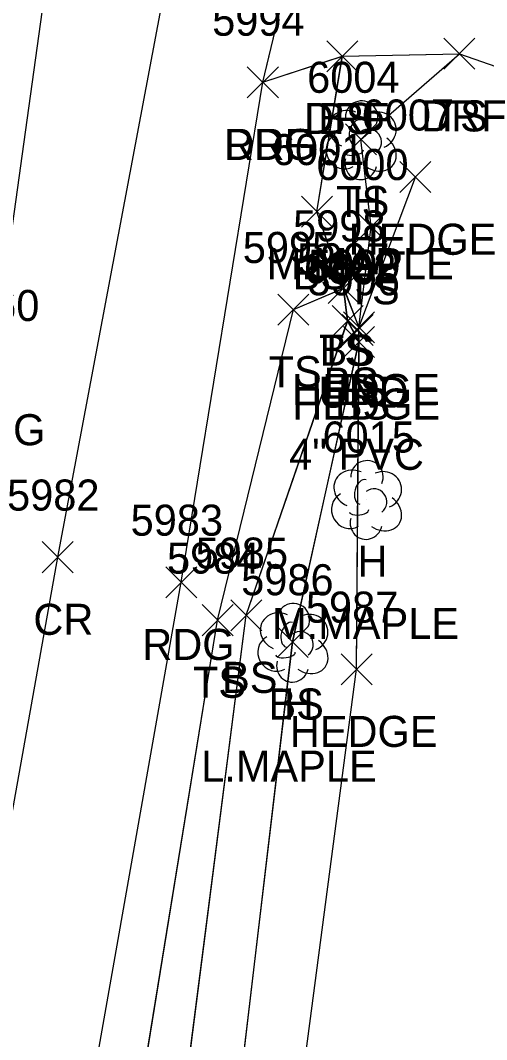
# Model space of a CAD drawing. Extents: x 1554668 to 1563881, y 831386 to 834374.
# Drawn here: x 1561932.8 to 1561962.8, y 834064.9 to 834130.6 of the extents above; entities that cross this region are included whole.
import ezdxf

# ---------------------------------------------------------------- set-up
doc = ezdxf.new("R2010")
doc.units = 0
for name, color, linetype in [('D_A', 7, 'Continuous'), ('D_C', 7, 'Continuous'), ('D_I', 7, 'Continuous'), ('D_TIC', 7, 'Continuous'), ('L_A', 7, 'Continuous'), ('L_C', 7, 'Continuous'), ('L_I', 7, 'Continuous'), ('L_TIC', 7, 'Continuous'), ('LAHR', 7, 'Continuous'), ('LELB', 7, 'Continuous'), ('LTD', 7, 'Continuous'), ('P_A', 7, 'Continuous'), ('P_I', 7, 'Continuous'), ('P_TIC', 7, 'Continuous'), ('PEU', 7, 'Continuous'), ('PRC', 7, 'Continuous'), ('R_A', 7, 'Continuous'), ('R_I', 7, 'Continuous'), ('R_TIC', 7, 'Continuous'), ('RDF', 7, 'Continuous')]:
    doc.layers.add(name, color=color, linetype=linetype)

msp = doc.modelspace()

# ---------------------------------------------------------------- linework, layer by layer
at = {"layer": 'D_TIC'}
for points in [[(1561953.528, 834109.622), (1561955.528, 834111.622)], [(1561955.528, 834109.622), (1561953.528, 834111.622)]]:
    msp.add_lwpolyline(points, dxfattribs=at)
at = {"layer": 'L_TIC'}
for points in [[(1561960.073, 834127.412), (1561962.073, 834129.412)], [(1561962.073, 834127.412), (1561960.073, 834129.412)], [(1561952.536, 834127.252), (1561954.536, 834129.252)], [(1561954.536, 834127.252), (1561952.536, 834129.252)], [(1561953.733, 834121.898), (1561955.733, 834123.898)], [(1561955.733, 834121.898), (1561953.733, 834123.898)], [(1561957.242, 834119.47), (1561959.242, 834121.47)], [(1561959.242, 834119.47), (1561957.242, 834121.47)], [(1561950.9, 834117.244), (1561952.9, 834119.244)], [(1561952.9, 834117.244), (1561950.9, 834119.244)], [(1561954.4, 834116.28), (1561956.4, 834118.28)], [(1561956.4, 834116.28), (1561954.4, 834118.28)], [(1561952.624, 834112.329), (1561954.624, 834114.329)], [(1561954.624, 834112.329), (1561952.624, 834114.329)], [(1561952.624, 834112.329), (1561954.624, 834114.329)], [(1561954.624, 834112.329), (1561952.624, 834114.329)], [(1561949.385, 834110.94), (1561951.385, 834112.94)], [(1561951.385, 834110.94), (1561949.385, 834112.94)], [(1561952.88, 834110.21), (1561954.88, 834112.21)], [(1561954.88, 834110.21), (1561952.88, 834112.21)], [(1561952.88, 834110.21), (1561954.88, 834112.21)], [(1561954.88, 834110.21), (1561952.88, 834112.21)], [(1561953.6, 834109.792), (1561955.6, 834111.792)], [(1561955.6, 834109.792), (1561953.6, 834111.792)], [(1561953.6, 834109.792), (1561955.6, 834111.792)], [(1561955.6, 834109.792), (1561953.6, 834111.792)], [(1561953.612, 834108.857), (1561955.612, 834110.857)], [(1561955.612, 834108.857), (1561953.612, 834110.857)], [(1561953.612, 834108.857), (1561955.612, 834110.857)], [(1561955.612, 834108.857), (1561953.612, 834110.857)], [(1561946.352, 834091.259), (1561948.352, 834093.259)], [(1561948.352, 834091.259), (1561946.352, 834093.259)], [(1561944.507, 834090.941), (1561946.507, 834092.941)], [(1561946.507, 834090.941), (1561944.507, 834092.941)], [(1561949.337, 834089.544), (1561951.337, 834091.544)], [(1561951.337, 834089.544), (1561949.337, 834091.544)], [(1561953.45, 834087.78), (1561955.45, 834089.78)], [(1561955.45, 834087.78), (1561953.45, 834089.78)]]:
    msp.add_lwpolyline(points, dxfattribs=at)
at = {"layer": 'LAHR'}
for points in [[(1561933.167, 833967.71), (1561943.911, 834017.246), (1561949.017, 834047.561), (1561954.45, 834088.78), (1561954.612, 834109.857), (1561954.6, 834110.792), (1561958.242, 834120.47)], [(1561933.168, 833967.708), (1561943.915, 834017.245), (1561949.015, 834047.561), (1561954.446, 834088.779), (1561954.608, 834109.856), (1561954.596, 834110.792), (1561958.243, 834120.47)], [(1561933.168, 833967.708), (1561943.915, 834017.245), (1561949.015, 834047.561), (1561954.446, 834088.779), (1561954.608, 834109.856), (1561954.596, 834110.792), (1561958.243, 834120.47)], [(1561933.168, 833967.708), (1561943.915, 834017.245), (1561949.015, 834047.561), (1561954.446, 834088.779), (1561954.608, 834109.856), (1561954.596, 834110.792), (1561958.243, 834120.47)]]:
    msp.add_lwpolyline(points, dxfattribs=at)
at = {"layer": 'LELB'}
for points in [[(1561890.593, 833773.388), (1561895.718, 833803.087), (1561903.038, 833845.228), (1561912.563, 833892.473), (1561912.525, 833900.106), (1561918.864, 833934.137), (1561920.901, 833947.117), (1561925.493, 833972.113), (1561933.777, 834019.881), (1561938.561, 834049.203), (1561945.505, 834091.941), (1561950.385, 834111.94), (1561953.62, 834113.327), (1561954.596, 834110.792), (1561955.401, 834117.28), (1561954.736, 834122.9), (1561961.072, 834128.412)], [(1561890.593, 833773.388), (1561895.718, 833803.087), (1561903.038, 833845.228), (1561912.563, 833892.473), (1561912.525, 833900.106), (1561918.864, 833934.137), (1561920.901, 833947.117), (1561925.493, 833972.113), (1561933.777, 834019.881), (1561938.561, 834049.203), (1561945.505, 834091.941), (1561950.385, 834111.94), (1561953.62, 834113.327), (1561954.596, 834110.792), (1561955.401, 834117.28), (1561954.736, 834122.9), (1561961.072, 834128.412)], [(1561890.593, 833773.388), (1561895.718, 833803.087), (1561903.038, 833845.228), (1561912.563, 833892.473), (1561912.525, 833900.106), (1561918.864, 833934.137), (1561920.901, 833947.117), (1561925.493, 833972.113), (1561933.777, 834019.881), (1561938.561, 834049.203), (1561945.505, 834091.941), (1561950.385, 834111.94), (1561953.62, 834113.327), (1561954.596, 834110.792), (1561955.401, 834117.28), (1561954.736, 834122.9), (1561961.072, 834128.412)], [(1561890.594, 833773.393), (1561895.717, 833803.083), (1561903.038, 833845.232), (1561912.562, 833892.472), (1561912.525, 833900.111), (1561918.862, 833934.133), (1561920.9, 833947.114), (1561925.493, 833972.114), (1561933.775, 834019.878), (1561938.557, 834049.204), (1561945.507, 834091.941), (1561950.385, 834111.94), (1561953.624, 834113.329), (1561954.6, 834110.792), (1561955.4, 834117.28), (1561954.733, 834122.898), (1561961.073, 834128.412)], [(1561923.916, 833946.356), (1561928.443, 833971.918), (1561936.647, 834019.209), (1561937.553, 834020.454), (1561941.755, 834048.637), (1561947.352, 834092.259), (1561953.88, 834111.21), (1561953.624, 834113.329), (1561951.9, 834118.244), (1561953.536, 834128.252)], [(1561923.917, 833946.355), (1561928.444, 833971.915), (1561936.648, 834019.206), (1561937.556, 834020.453), (1561941.757, 834048.637), (1561947.351, 834092.259), (1561953.877, 834111.209), (1561953.62, 834113.327), (1561951.896, 834118.243), (1561953.535, 834128.252)], [(1561923.917, 833946.355), (1561928.444, 833971.915), (1561936.648, 834019.206), (1561937.556, 834020.453), (1561941.757, 834048.637), (1561947.351, 834092.259), (1561953.877, 834111.209), (1561953.62, 834113.327), (1561951.896, 834118.243), (1561953.535, 834128.252)], [(1561923.917, 833946.355), (1561928.444, 833971.915), (1561936.648, 834019.206), (1561937.556, 834020.453), (1561941.757, 834048.637), (1561947.351, 834092.259), (1561953.877, 834111.209), (1561953.62, 834113.327), (1561951.896, 834118.243), (1561953.535, 834128.252)], [(1561956.838, 833935.82), (1561944.784, 833952.217), (1561933.167, 833967.71), (1561942.405, 834017.989), (1561945.385, 834048.678), (1561950.337, 834090.544), (1561954.612, 834109.857), (1561953.88, 834111.21)], [(1561956.839, 833935.82), (1561944.785, 833952.215), (1561933.168, 833967.708), (1561942.401, 834017.991), (1561945.381, 834048.679), (1561950.339, 834090.544), (1561954.608, 834109.856), (1561953.877, 834111.209)], [(1561956.839, 833935.82), (1561944.785, 833952.215), (1561933.168, 833967.708), (1561942.401, 834017.991), (1561945.381, 834048.679), (1561950.339, 834090.544), (1561954.608, 834109.856), (1561953.877, 834111.209)], [(1561956.839, 833935.82), (1561944.785, 833952.215), (1561933.168, 833967.708), (1561942.401, 834017.991), (1561945.381, 834048.679), (1561950.339, 834090.544), (1561954.608, 834109.856), (1561953.877, 834111.209)]]:
    msp.add_lwpolyline(points, dxfattribs=at)
at = {"layer": 'LTD'}
for p, q in [((1561954.733, 834122.898), (1561954.733, 834122.898)), ((1561954.733, 834122.898), (1561954.733, 834122.898)), ((1561955.075, 834099.735), (1561955.075, 834099.735)), ((1561955.075, 834099.735), (1561955.075, 834099.735)), ((1561950.337, 834090.544), (1561950.337, 834090.544)), ((1561950.337, 834090.544), (1561950.337, 834090.544))]:
    msp.add_line(p, q, dxfattribs=at)
for centre in [(1561954.779, 834124.332), (1561955.121, 834101.169), (1561950.383, 834091.978)]:
    msp.add_arc(centre, 1.047, 335.52715, 180.95627, dxfattribs=at)
for centre, major_axis, ratio, start_param, end_param in [((1561953.941, 834123.565), (1.21, -0.512), 0.895232, 1.570796, 4.712389), ((1561955.774, 834123.482), (-1.141, -0.483), 0.949671, 1.570796, 4.712389), ((1561954.524, 834123.357), (-0.208, -0.792), 0.645439, 3.141593, 6.283185), ((1561955.233, 834122.732), (-0.5, 0.667), 0.989748, 3.141593, 6.283185), ((1561953.649, 834122.19), (0.584, -1.042), 0.959034, 3.141593, 6.283185), ((1561955.733, 834122.065), (-1.09, 0.792), 0.841452, 1.570796, 4.712389), ((1561954.274, 834122.148), (-0.625, -0.083), 0.423636, 0, 3.141593), ((1561954.733, 834121.398), (0.265, 1.061), 0.942809, 1.570796, 4.712389), ((1561954.283, 834100.401), (1.21, -0.512), 0.895232, 1.570796, 4.712389), ((1561956.116, 834100.318), (-1.141, -0.483), 0.949671, 1.570796, 4.712389), ((1561954.866, 834100.193), (-0.208, -0.792), 0.645439, 3.141593, 6.283185), ((1561955.575, 834099.568), (-0.5, 0.667), 0.989748, 3.141593, 6.283185), ((1561953.992, 834099.026), (0.584, -1.042), 0.959034, 3.141593, 6.283185), ((1561956.075, 834098.901), (-1.09, 0.792), 0.841452, 1.570796, 4.712389), ((1561955.075, 834098.235), (0.265, 1.061), 0.942809, 1.570796, 4.712389), ((1561954.617, 834098.985), (-0.625, -0.083), 0.423636, 0, 3.141593), ((1561949.545, 834091.211), (1.21, -0.512), 0.895232, 1.570796, 4.712389), ((1561951.378, 834091.128), (-1.141, -0.483), 0.949671, 1.570796, 4.712389), ((1561950.128, 834091.003), (-0.208, -0.792), 0.645439, 3.141593, 6.283185), ((1561950.837, 834090.378), (-0.5, 0.667), 0.989748, 3.141593, 6.283185), ((1561949.253, 834089.836), (0.584, -1.042), 0.959034, 3.141593, 6.283185), ((1561951.337, 834089.711), (-1.09, 0.792), 0.841452, 1.570796, 4.712389), ((1561950.337, 834089.044), (0.265, 1.061), 0.942809, 1.570796, 4.712389), ((1561949.878, 834089.794), (-0.625, -0.083), 0.423636, 0, 3.141593)]:
    msp.add_ellipse(centre, major_axis=major_axis, ratio=ratio, start_param=start_param, end_param=end_param, dxfattribs=at)
at = {"layer": 'P_TIC'}
for points in [[(1561947.417, 834125.574), (1561949.417, 834127.574)], [(1561949.417, 834125.574), (1561947.417, 834127.574)], [(1561934.214, 834094.998), (1561936.214, 834096.998)], [(1561936.214, 834094.998), (1561934.214, 834096.998)], [(1561942.167, 834093.381), (1561944.167, 834095.381)], [(1561944.167, 834093.381), (1561942.167, 834095.381)]]:
    msp.add_lwpolyline(points, dxfattribs=at)
at = {"layer": 'PEU'}
for points in [[(1561919.943, 834298.234), (1561943.28, 834270.95), (1561951.487, 834242.498), (1561947.428, 834199.982), (1561938.335, 834160.955), (1561930.989, 834108.205), (1561926.196, 834084.148), (1561918.625, 834048.817), (1561911.303, 834007.014), (1561902.907, 833960.116), (1561894.327, 833910.706), (1561885.392, 833863.263), (1561878.367, 833822.842), (1561871.83, 833787.475), (1561866.706, 833759.336), (1561861.912, 833735.821)], [(1561919.942, 834298.234), (1561943.28, 834270.951), (1561951.486, 834242.497), (1561947.431, 834199.985), (1561938.334, 834160.954), (1561930.992, 834108.207), (1561926.199, 834084.149), (1561918.629, 834048.816), (1561911.301, 834007.016), (1561902.906, 833960.119), (1561894.326, 833910.708), (1561885.391, 833863.267), (1561878.367, 833822.843), (1561871.83, 833787.477), (1561866.708, 833759.341), (1561861.913, 833735.821)], [(1561919.942, 834298.234), (1561943.28, 834270.951), (1561951.486, 834242.497), (1561947.431, 834199.985), (1561938.334, 834160.954), (1561930.992, 834108.207), (1561926.199, 834084.149), (1561918.629, 834048.816), (1561911.301, 834007.016), (1561902.906, 833960.119), (1561894.326, 833910.708), (1561885.391, 833863.267), (1561878.367, 833822.843), (1561871.83, 833787.477), (1561866.708, 833759.341), (1561861.913, 833735.821)], [(1561919.942, 834298.234), (1561943.28, 834270.951), (1561951.486, 834242.497), (1561947.431, 834199.985), (1561938.334, 834160.954), (1561930.992, 834108.207), (1561926.199, 834084.149), (1561918.629, 834048.816), (1561911.301, 834007.016), (1561902.906, 833960.119), (1561894.326, 833910.708), (1561885.391, 833863.267), (1561878.367, 833822.843), (1561871.83, 833787.477), (1561866.708, 833759.341), (1561861.913, 833735.821)], [(1561874.546, 833715.874), (1561887.478, 833772.584), (1561893.313, 833803.99), (1561901.362, 833845.453), (1561909.68, 833892.69), (1561910.734, 833900.622), (1561917.511, 833934.31), (1561919.487, 833947.442), (1561923.612, 833973.077), (1561931.593, 834020.004), (1561935.393, 834050.314), (1561943.165, 834094.381), (1561948.419, 834126.576), (1561953.285, 834146.878), (1561956.677, 834158.88)], [(1561874.546, 833715.874), (1561887.478, 833772.584), (1561893.313, 833803.99), (1561901.362, 833845.453), (1561909.68, 833892.69), (1561910.734, 833900.622), (1561917.511, 833934.31), (1561919.487, 833947.442), (1561923.612, 833973.077), (1561931.593, 834020.004), (1561935.393, 834050.314), (1561943.165, 834094.381), (1561948.419, 834126.576), (1561953.285, 834146.878), (1561956.677, 834158.88)], [(1561874.546, 833715.874), (1561887.478, 833772.584), (1561893.313, 833803.99), (1561901.362, 833845.453), (1561909.68, 833892.69), (1561910.734, 833900.622), (1561917.511, 833934.31), (1561919.487, 833947.442), (1561923.612, 833973.077), (1561931.593, 834020.004), (1561935.393, 834050.314), (1561943.165, 834094.381), (1561948.419, 834126.576), (1561953.285, 834146.878), (1561956.677, 834158.88)], [(1561874.547, 833715.877), (1561887.477, 833772.582), (1561893.312, 833803.991), (1561901.361, 833845.451), (1561909.679, 833892.687), (1561910.732, 833900.62), (1561917.51, 833934.306), (1561919.486, 833947.443), (1561923.61, 833973.073), (1561931.592, 834020.003), (1561935.394, 834050.314), (1561943.167, 834094.381), (1561948.417, 834126.574), (1561953.283, 834146.877), (1561956.677, 834158.88)]]:
    msp.add_lwpolyline(points, dxfattribs=at)
at = {"layer": 'PRC'}
for points in [[(1561800.21, 833371.538), (1561806.437, 833405.192), (1561812.654, 833434.931), (1561820.127, 833472.189), (1561827.528, 833505.749), (1561836.938, 833558.608), (1561848.037, 833617.29), (1561858.182, 833669.762), (1561866.962, 833717.246), (1561878.604, 833773.781), (1561885.024, 833806.831), (1561891.658, 833847.81), (1561899.783, 833893.72), (1561902.023, 833902.922), (1561908.115, 833944.075), (1561914.56, 833974.526), (1561922.248, 834021.375), (1561927.368, 834052.029), (1561935.214, 834095.998), (1561945.529, 834150.774)], [(1561800.212, 833371.537), (1561806.439, 833405.19), (1561812.656, 833434.927), (1561820.128, 833472.18), (1561827.529, 833505.744), (1561836.939, 833558.603), (1561848.037, 833617.288), (1561858.18, 833669.759), (1561866.961, 833717.243), (1561878.605, 833773.781), (1561885.024, 833806.829), (1561891.662, 833847.808), (1561899.784, 833893.716), (1561902.024, 833902.921), (1561908.116, 833944.071), (1561914.561, 833974.522), (1561922.249, 834021.372), (1561927.371, 834052.029), (1561935.212, 834095.998), (1561945.527, 834150.773)], [(1561800.212, 833371.537), (1561806.439, 833405.19), (1561812.656, 833434.927), (1561820.128, 833472.18), (1561827.529, 833505.744), (1561836.939, 833558.603), (1561848.037, 833617.288), (1561858.18, 833669.759), (1561866.961, 833717.243), (1561878.605, 833773.781), (1561885.024, 833806.829), (1561891.662, 833847.808), (1561899.784, 833893.716), (1561902.024, 833902.921), (1561908.116, 833944.071), (1561914.561, 833974.522), (1561922.249, 834021.372), (1561927.371, 834052.029), (1561935.212, 834095.998), (1561945.527, 834150.773)], [(1561800.212, 833371.537), (1561806.439, 833405.19), (1561812.656, 833434.927), (1561820.128, 833472.18), (1561827.529, 833505.744), (1561836.939, 833558.603), (1561848.037, 833617.288), (1561858.18, 833669.759), (1561866.961, 833717.243), (1561878.605, 833773.781), (1561885.024, 833806.829), (1561891.662, 833847.808), (1561899.784, 833893.716), (1561902.024, 833902.921), (1561908.116, 833944.071), (1561914.561, 833974.522), (1561922.249, 834021.372), (1561927.371, 834052.029), (1561935.212, 834095.998), (1561945.527, 834150.773)]]:
    msp.add_lwpolyline(points, dxfattribs=at)
at = {"layer": 'R_TIC'}
for points in [[(1561960.073, 834127.412), (1561962.073, 834129.412)], [(1561962.073, 834127.412), (1561960.073, 834129.412)], [(1561952.536, 834127.252), (1561954.536, 834129.252)], [(1561954.536, 834127.252), (1561952.536, 834129.252)], [(1561947.417, 834125.574), (1561949.417, 834127.574)], [(1561949.417, 834125.574), (1561947.417, 834127.574)]]:
    msp.add_lwpolyline(points, dxfattribs=at)
at = {"layer": 'RDF'}
for points in [[(1561948.417, 834126.574), (1561953.536, 834128.252), (1561961.073, 834128.412), (1561971.48, 834124.79), (1561973.395, 834137.986), (1561961.731, 834141.224), (1561953.283, 834146.877)], [(1561948.419, 834126.576), (1561953.535, 834128.252), (1561961.072, 834128.412), (1561971.478, 834124.789), (1561973.394, 834137.986), (1561961.727, 834141.222), (1561953.285, 834146.878)], [(1561948.419, 834126.576), (1561953.535, 834128.252), (1561961.072, 834128.412), (1561971.478, 834124.789), (1561973.394, 834137.986), (1561961.727, 834141.222), (1561953.285, 834146.878)], [(1561948.419, 834126.576), (1561953.535, 834128.252), (1561961.072, 834128.412), (1561971.478, 834124.789), (1561973.394, 834137.986), (1561961.727, 834141.222), (1561953.285, 834146.878)]]:
    msp.add_lwpolyline(points, dxfattribs=at)

# ---------------------------------------------------------------- texts
at = {"layer": 'D_A'}
msp.add_text('UND', height=2, dxfattribs=at).set_placement((1561952.001, 834105.622))
at = {"layer": 'D_C'}
msp.add_text('4" PVC', height=2, dxfattribs=at).set_placement((1561950.111, 834101.622))
at = {"layer": 'D_I'}
msp.add_text('6002', height=2, dxfattribs=at).set_placement((1561951.064, 834113.622))
at = {"layer": 'L_A'}
for s, p in [('TS', (1561959.482, 834123.412)), ('BS', (1561951.977, 834123.252)), ('TS', (1561953.142, 834117.898)), ('H', (1561954.166, 834117.898)), ('HEDGE', (1561953.942, 834115.47)), ('BS', (1561950.341, 834113.244)), ('TS', (1561953.81, 834112.28)), ('TS', (1561952.033, 834108.329)), ('BS', (1561952.065, 834108.329)), ('TS', (1561948.794, 834106.94)), ('HEDGE', (1561950.301, 834105.792)), ('BS', (1561952.321, 834106.21)), ('BS', (1561952.321, 834106.21)), ('TS', (1561953.009, 834105.792)), ('HEDGE', (1561950.313, 834104.857)), ('BS', (1561953.053, 834104.857)), ('H', (1561954.508, 834094.735)), ('BS', (1561945.793, 834087.259)), ('TS', (1561943.917, 834086.941)), ('BS', (1561948.778, 834085.544)), ('H', (1561949.77, 834085.544)), ('HEDGE', (1561950.151, 834083.78))]:
    msp.add_text(s, height=2, dxfattribs=at).set_placement(p)
at = {"layer": 'L_C'}
for s, p in [('M.MAPLE', (1561948.67, 834113.898)), ('M.MAPLE', (1561949.012, 834090.735)), ('L.MAPLE', (1561944.447, 834081.544))]:
    msp.add_text(s, height=2, dxfattribs=at).set_placement(p)
at = {"layer": 'L_I'}
for s, p in [('6004', (1561951.268, 834125.898)), ('6004', (1561951.268, 834125.898)), ('6007', (1561954.777, 834123.47)), ('6001', (1561949.003, 834121.244)), ('6000', (1561951.849, 834120.28)), ('5998', (1561950.364, 834116.329)), ('5998', (1561950.364, 834116.329)), ('5995', (1561947.125, 834114.94)), ('5997', (1561950.62, 834114.21)), ('5997', (1561950.62, 834114.21)), ('5999', (1561951.332, 834113.792)), ('5999', (1561951.332, 834113.792)), ('5996', (1561951.297, 834112.857)), ('5996', (1561951.297, 834112.857)), ('6015', (1561952.256, 834102.735)), ('5985', (1561944.093, 834095.259)), ('5984', (1561942.248, 834094.941)), ('5986', (1561947.022, 834093.544)), ('5986', (1561947.022, 834093.544)), ('5987', (1561951.19, 834091.78))]:
    msp.add_text(s, height=2, dxfattribs=at).set_placement(p)
at = {"layer": 'P_A'}
for s, p in [('RDG', (1561945.905, 834121.574)), ('RDG', (1561928.477, 834103.205)), ('CR', (1561933.647, 834090.998)), ('RDG', (1561940.655, 834089.381))]:
    msp.add_text(s, height=2, dxfattribs=at).set_placement(p)
at = {"layer": 'P_I'}
for s, p in [('5994', (1561945.157, 834129.574)), ('1060', (1561928.084, 834111.205)), ('5982', (1561931.954, 834098.998)), ('5983', (1561939.907, 834097.381))]:
    msp.add_text(s, height=2, dxfattribs=at).set_placement(p)
at = {"layer": 'R_A'}
for p in [(1561958.608, 834123.412), (1561951.071, 834123.252), (1561945.952, 834121.574)]:
    msp.add_text('DRF', height=2, dxfattribs=at).set_placement(p)
at = {"layer": 'R_I'}
msp.add_text('5994', height=2, dxfattribs=at).set_placement((1561945.157, 834129.574))

doc.saveas('drawing.dxf')
